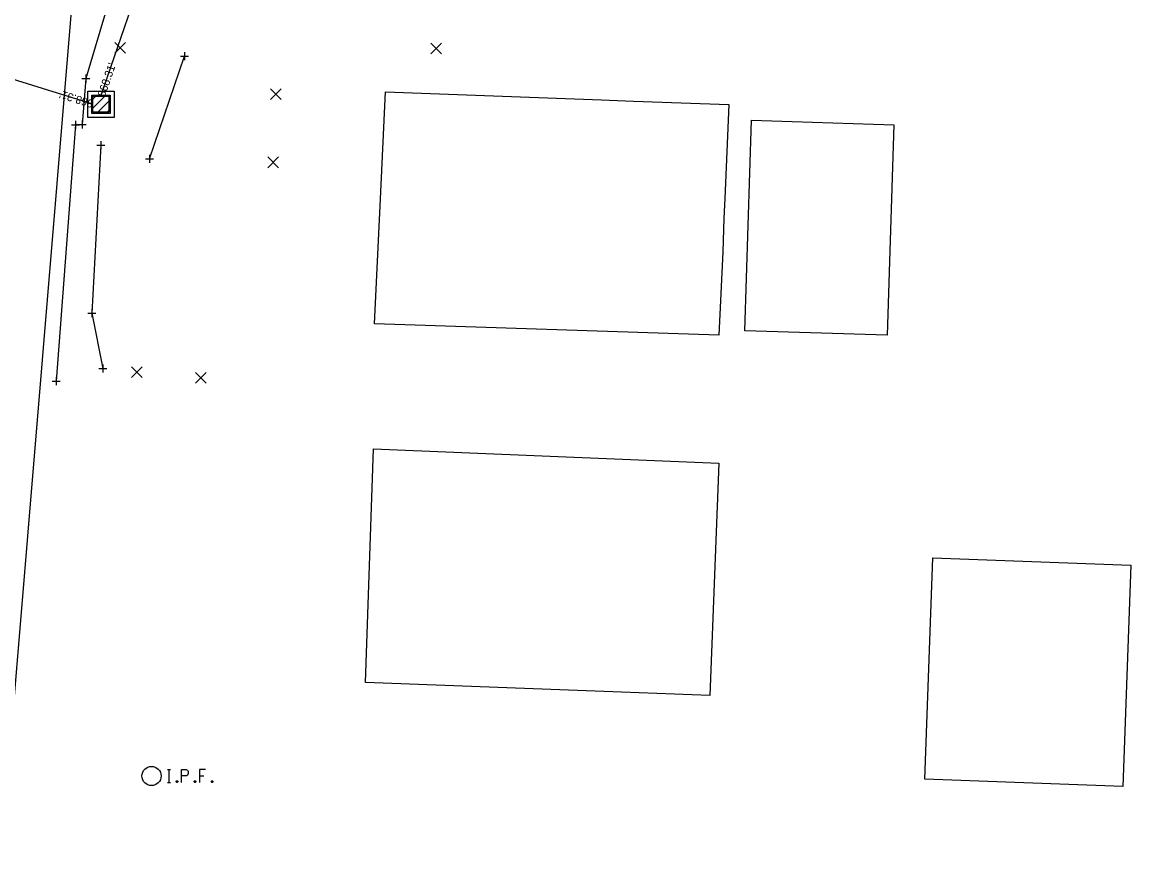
# Model space of a CAD drawing. Extents: x 1380440 to 1381945, y 468756 to 470369.
# Drawn here: x 1381624.1 to 1381762.6, y 470102.7 to 470207.8 of the extents above; entities that cross this region are included whole.
import ezdxf

# ---------------------------------------------------------------- set-up
doc = ezdxf.new("R2010")
doc.units = 0
for name, color, linetype in [('BD_X_Building', 7, 'Continuous'), ('GE_P_Driveway_CL', 7, 'Continuous'), ('PV_P_Curb', 7, 'Continuous'), ('PV_P_Curb_Ramp', 7, 'Continuous'), ('PV_P_Joint', 7, 'Continuous'), ('PV_P_Parking_Lot', 7, 'Continuous'), ('RW_P_Esmt_TMP', 7, 'Continuous'), ('SC_Scratch1', 7, 'Continuous'), ('SC_Shading3', 7, 'Continuous'), ('SH_Named_Boundary', 7, 'Continuous'), ('UT_X_Water', 7, 'Continuous'), ('X-CL', 7, 'Continuous')]:
    doc.layers.add(name, color=color, linetype=linetype)

msp = doc.modelspace()

# ---------------------------------------------------------------- linework, layer by layer
at = {"layer": 'BD_X_Building'}
for points in [[(1381700.47, 470197.96), (1381712.35, 470197.53), (1381711.85, 470185.81), (1381711.72, 470183.34), (1381711.6, 470179.12), (1381711.1, 470168.71), (1381668.09, 470170.12), (1381668.84, 470185.77), (1381669.47, 470199.12), (1381696.47, 470198.12)], [(1381714.35, 470169.27), (1381715.19, 470195.56), (1381732.99, 470194.99), (1381732.15, 470168.7)], [(1381709.97, 470123.71), (1381698.97, 470124.11), (1381666.97, 470125.33), (1381667.97, 470154.52), (1381711.1, 470152.71)], [(1381761.6, 470112.33), (1381736.85, 470113.24), (1381737.85, 470140.9), (1381762.6, 470139.99)]]:
    msp.add_lwpolyline(points, close=True, dxfattribs=at)
at = {"layer": 'GE_P_Driveway_CL'}
for p, q in [((1381635.64, 470203.94), (1381636.98, 470205.27)), ((1381635.64, 470205.27), (1381636.98, 470203.94)), ((1381675.11, 470203.86), (1381676.44, 470205.2)), ((1381675.11, 470205.2), (1381676.44, 470203.86)), ((1381655.08, 470198.14), (1381656.41, 470199.48)), ((1381655.08, 470199.48), (1381656.41, 470198.14)), ((1381654.74, 470189.64), (1381656.08, 470190.98)), ((1381654.74, 470190.98), (1381656.08, 470189.64)), ((1381637.71, 470163.41), (1381639.04, 470164.75)), ((1381637.71, 470164.75), (1381639.04, 470163.41)), ((1381645.71, 470162.72), (1381647.04, 470164.06)), ((1381645.71, 470164.06), (1381647.04, 470162.72))]:
    msp.add_line(p, q, dxfattribs=at)
at = {"layer": 'PV_P_Curb'}
msp.add_lwpolyline([(1381633.88, 470192.46), (1381632.76, 470171.45), (1381634.14, 470164.55)], dxfattribs=at)
at = {"layer": 'PV_P_Curb_Ramp'}
for p, q in [((1381633.9, 470199.22), (1381633.9, 470199.22)), ((1381632.9, 470197.56), (1381632.9, 470197.56)), ((1381633.9, 470198.56), (1381633.9, 470198.56)), ((1381633.9, 470197.56), (1381633.9, 470197.56)), ((1381633.9, 470197.56), (1381633.9, 470197.56)), ((1381633.9, 470197.56), (1381633.9, 470197.56)), ((1381634.9, 470197.56), (1381634.9, 470197.56)), ((1381633.9, 470196.56), (1381633.9, 470196.56)), ((1381633.9, 470195.89), (1381633.9, 470195.89))]:
    msp.add_line(p, q, dxfattribs=at)
at = {"layer": 'PV_P_Joint'}
for p, q in [((1381632.76, 470196.94), (1381634.52, 470198.7)), ((1381632.76, 470198.08), (1381633.38, 470198.7)), ((1381633.36, 470196.41), (1381635.05, 470198.1)), ((1381634.49, 470196.41), (1381635.05, 470196.97))]:
    msp.add_line(p, q, dxfattribs=at)
for points in [[(1381632.24, 470199.22), (1381635.57, 470199.22), (1381635.57, 470195.89), (1381632.24, 470195.89)], [(1381632.76, 470198.7), (1381635.05, 470198.7), (1381635.05, 470196.41), (1381632.76, 470196.41)], [(1381632.9, 470198.56), (1381634.9, 470198.56), (1381634.9, 470196.56), (1381632.9, 470196.56)]]:
    msp.add_lwpolyline(points, close=True, dxfattribs=at)
at = {"layer": 'PV_P_Parking_Lot'}
msp.add_lwpolyline([(1381639.97, 470190.75), (1381644.33, 470203.57)], dxfattribs=at)
at = {"layer": 'RW_P_Esmt_TMP'}
msp.add_lwpolyline([(1381676.76, 470220.38), (1381671.71, 470220.3), (1381655.72, 470220.85), (1381645.83, 470219.4), (1381641.21, 470217.31), (1381638.62, 470215.56), (1381638.59, 470214.96), (1381636.76, 470213.19), (1381634.36, 470208.62), (1381632.01, 470200.77), (1381631.56, 470195.02), (1381630.71, 470195), (1381628.3, 470162.98)], dxfattribs=at)
at = {"layer": 'SC_Scratch1'}
for points in [[(1381642.23, 470114.45), (1381642.59, 470114.45)], [(1381642.41, 470112.85), (1381642.41, 470114.45)], [(1381643.97, 470112.85), (1381643.97, 470114.45), (1381644.5, 470114.45), (1381644.56, 470114.44), (1381644.64, 470114.41), (1381644.67, 470114.39), (1381644.7, 470114.36), (1381644.75, 470114.3), (1381644.78, 470114.24), (1381644.8, 470114.14), (1381644.8, 470113.98), (1381644.79, 470113.93), (1381644.77, 470113.86), (1381644.72, 470113.77), (1381644.68, 470113.73), (1381644.65, 470113.71), (1381644.59, 470113.68), (1381644.5, 470113.67), (1381643.97, 470113.67)], [(1381646.98, 470114.45), (1381646.22, 470114.45), (1381646.22, 470112.85)], [(1381643.37, 470113.06), (1381643.42, 470113.06), (1381643.46, 470113.04), (1381643.49, 470112.99), (1381643.49, 470112.93), (1381643.46, 470112.88), (1381643.42, 470112.85), (1381643.37, 470112.85), (1381643.33, 470112.88), (1381643.3, 470112.93), (1381643.3, 470112.99), (1381643.33, 470113.04), (1381643.37, 470113.06)], [(1381645.62, 470113.06), (1381645.67, 470113.06), (1381645.7, 470113.04), (1381645.74, 470112.99), (1381645.74, 470112.93), (1381645.7, 470112.88), (1381645.67, 470112.85), (1381645.62, 470112.85), (1381645.58, 470112.88), (1381645.55, 470112.93), (1381645.55, 470112.99), (1381645.58, 470113.04), (1381645.62, 470113.06)], [(1381646.22, 470113.67), (1381646.76, 470113.67)], [(1381647.77, 470113.06), (1381647.82, 470113.06), (1381647.85, 470113.04), (1381647.89, 470112.99), (1381647.89, 470112.93), (1381647.85, 470112.88), (1381647.82, 470112.85), (1381647.77, 470112.85), (1381647.73, 470112.88), (1381647.7, 470112.93), (1381647.7, 470112.99), (1381647.73, 470113.04), (1381647.77, 470113.06)], [(1381642.23, 470112.85), (1381642.59, 470112.85)]]:
    msp.add_lwpolyline(points, dxfattribs=at)
msp.add_circle((1381640.22, 470113.65), 1.2, dxfattribs=at)
at = {"layer": 'SC_Shading3'}
for points in [[(1381714.35, 470169.27), (1381715.19, 470195.56), (1381732.99, 470194.99), (1381732.15, 470168.7)], [(1381761.6, 470112.33), (1381736.85, 470113.24), (1381737.85, 470140.9), (1381762.6, 470139.99)]]:
    msp.add_lwpolyline(points, close=True, dxfattribs=at)
at = {"layer": 'SH_Named_Boundary'}
for p, q in [((1381643.83, 470203.57), (1381644.83, 470203.57)), ((1381644.33, 470204.07), (1381644.33, 470203.07)), ((1381644.33, 470203.57), (1381644.33, 470203.57)), ((1381631.51, 470200.77), (1381632.51, 470200.77)), ((1381631.51, 470200.77), (1381632.51, 470200.77)), ((1381632.01, 470201.27), (1381632.01, 470200.27)), ((1381632.01, 470201.27), (1381632.01, 470200.27)), ((1381632.01, 470200.77), (1381632.01, 470200.77)), ((1381632.01, 470200.77), (1381632.01, 470200.77)), ((1381630.21, 470195), (1381631.21, 470195)), ((1381630.71, 470195.5), (1381630.71, 470194.5)), ((1381630.71, 470195), (1381630.71, 470195)), ((1381631.06, 470195.02), (1381632.06, 470195.02)), ((1381631.56, 470195.52), (1381631.56, 470194.52)), ((1381631.56, 470195.02), (1381631.56, 470195.02)), ((1381633.38, 470192.46), (1381634.38, 470192.46)), ((1381633.88, 470192.96), (1381633.88, 470191.96)), ((1381633.88, 470192.46), (1381633.88, 470192.46)), ((1381639.47, 470190.75), (1381640.47, 470190.75)), ((1381639.97, 470191.25), (1381639.97, 470190.25)), ((1381639.97, 470190.75), (1381639.97, 470190.75)), ((1381632.26, 470171.45), (1381633.26, 470171.45)), ((1381632.76, 470171.95), (1381632.76, 470170.95)), ((1381632.76, 470171.45), (1381632.76, 470171.45)), ((1381633.64, 470164.55), (1381634.64, 470164.55)), ((1381634.14, 470165.05), (1381634.14, 470164.05)), ((1381634.14, 470164.55), (1381634.14, 470164.55)), ((1381627.8, 470162.98), (1381628.8, 470162.98)), ((1381628.3, 470163.48), (1381628.3, 470162.48)), ((1381628.3, 470162.98), (1381628.3, 470162.98))]:
    msp.add_line(p, q, dxfattribs=at)
at = {"layer": 'UT_X_Water'}
msp.add_line((1381545.41, 469194.71), (1381630.26, 470209.69), dxfattribs=at)
at = {"layer": 'X-CL'}
for p, q in [((1381633.9, 470198.56), (1381646.79, 470236.27)), ((1381632.9, 470197.56), (1381601.08, 470207.52))]:
    msp.add_line(p, q, dxfattribs=at)

# ---------------------------------------------------------------- texts
at = {"layer": 'SC_Scratch1'}
for rotation, p in [(71.1297, (1381634.38, 470198.4)), (162.6187, (1381633.05, 470198.03))]:
    msp.add_text("868.31'", height=1, rotation=rotation, dxfattribs=at).set_placement(p)

doc.saveas('drawing.dxf')
